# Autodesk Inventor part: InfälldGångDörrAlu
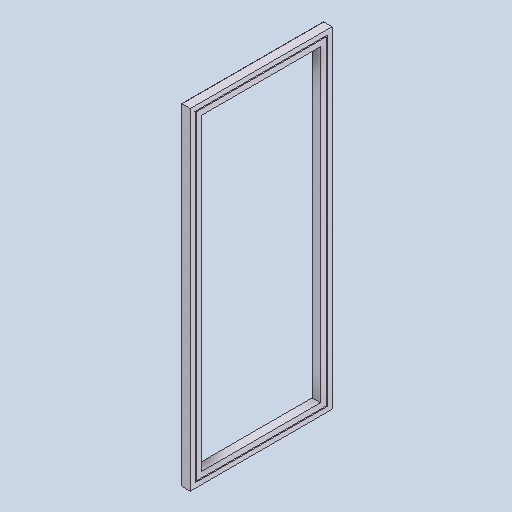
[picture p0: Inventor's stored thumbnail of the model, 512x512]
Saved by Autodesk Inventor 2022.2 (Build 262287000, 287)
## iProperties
Created: 2022-02
Part Number: InfälldGångDörrAlu
Material: Aluminum 6061, Welded
Document SubType Name: Modeling
Designer: cl
Density: 2.7 g/cm^3
Appearance: Weld - Aluminum
Author: cl
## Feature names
1. Extrusion1
2. Sweep1
## Parameters: BladBredd = 987.5 mm, Fönsterhöjd = 862 mm, Blad2 = 1012.5 mm, Blad3 = 0, Blad4 = 0, Blad5 = 1012.5 mm, Blad6 = 2025 mm, MGJ12Djup = 0, MGJ12Bredd = 0, MGJ2Djup = 0, MGJ2Bredd = 5012.5 mm, MGJ56Djup = 0, MGJ56Bredd = 0, MGJ23Djup = 48 mm, MGJ45Djup = 48 mm, GarageRegel5 = 0, GarageRegel6 = 0, Styrrulle2Djup = 0, FönsterhöjdStyrning = 862 mm, FönsterKarm = 54 mm, AndraGlasraden = 0, BrösthöjdStyrning2 = 0.0001 mm, InfälldGångDörr = 0, Infälldstyr = 1012.5 mm, d0 = 817.5 mm, d1 = 1991 mm, d4 = 6 mm, d5 = 41 mm, d6 = 52 mm, d7 = 0, d16 = 0, d17 = 0, d21 = 5 mm, d22 = 25 mm, d23 = 12 mm, d25 = 5 mm, d27 = 45 mm, d28 = 4 mm
